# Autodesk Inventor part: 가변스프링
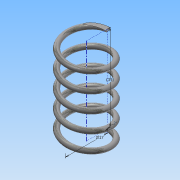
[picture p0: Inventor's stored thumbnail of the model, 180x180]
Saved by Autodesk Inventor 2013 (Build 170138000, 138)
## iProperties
Created: 2017-02
Part Number: 가변스프링
Material: 강철, 탄소
Document SubType Name: Modeling
Designer: Administrator
Mass: 6.51392 g
Surface Area: 16.803 cm^2
Volume: 0.82769 cm^3
Density: 7.87 g/cm^3
Author: Administrator
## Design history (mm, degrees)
sketch "스케치1"
  geometry: L1 (0, 0)-(8.5, 0); L2 (8.5, 0)-(8.5, 35); L3 (8.5, 35)-(0, 35); L4 (0, 35)-(0, 0); C1 r 1 at (8.5, 0)
  constraints: 8 end point, 2 parallel, 1 centre point, 1 coincident, 1 horizontal, 1 perpendicular
  dimensions: "d0" = 2 diameter of C1; "d2" = 17 diameter of L2 L4; "d3" = 35 distance of L1.end L2.end (derived)
feature "코일1" sketch "스케치1" pitch "d4" = 10; turns "d6" = 5; dims "d5" = 35 (= d3), "d7" = 0, angle "d8" = 90 deg, angle "d9" = 90 deg, "d10" = 0, "d11" = 0
sketch "스케치2"
  geometry: L1 (0, 7.5)-(0, 9.5) reference; 1 further point
  constraints: 1 vertical alignment
extrude "돌출1" cut sketch "스케치2" stored distance "d12" = 10; taper "d13" = 0 deg
node "작업 평면1"
sketch "스케치3"
  geometry: L1 (0, 9.5)-(0, 7.5) reference; 1 further point
  constraints: 1 vertical alignment
extrude "돌출2" cut sketch "스케치3" stored distance "d14" = 10; taper "d15" = 0 deg
node "솔리드1"
node "절단 모서리 투영1"
node "절단 모서리 투영2"
